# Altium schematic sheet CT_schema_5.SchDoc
size 454 x 430 mm
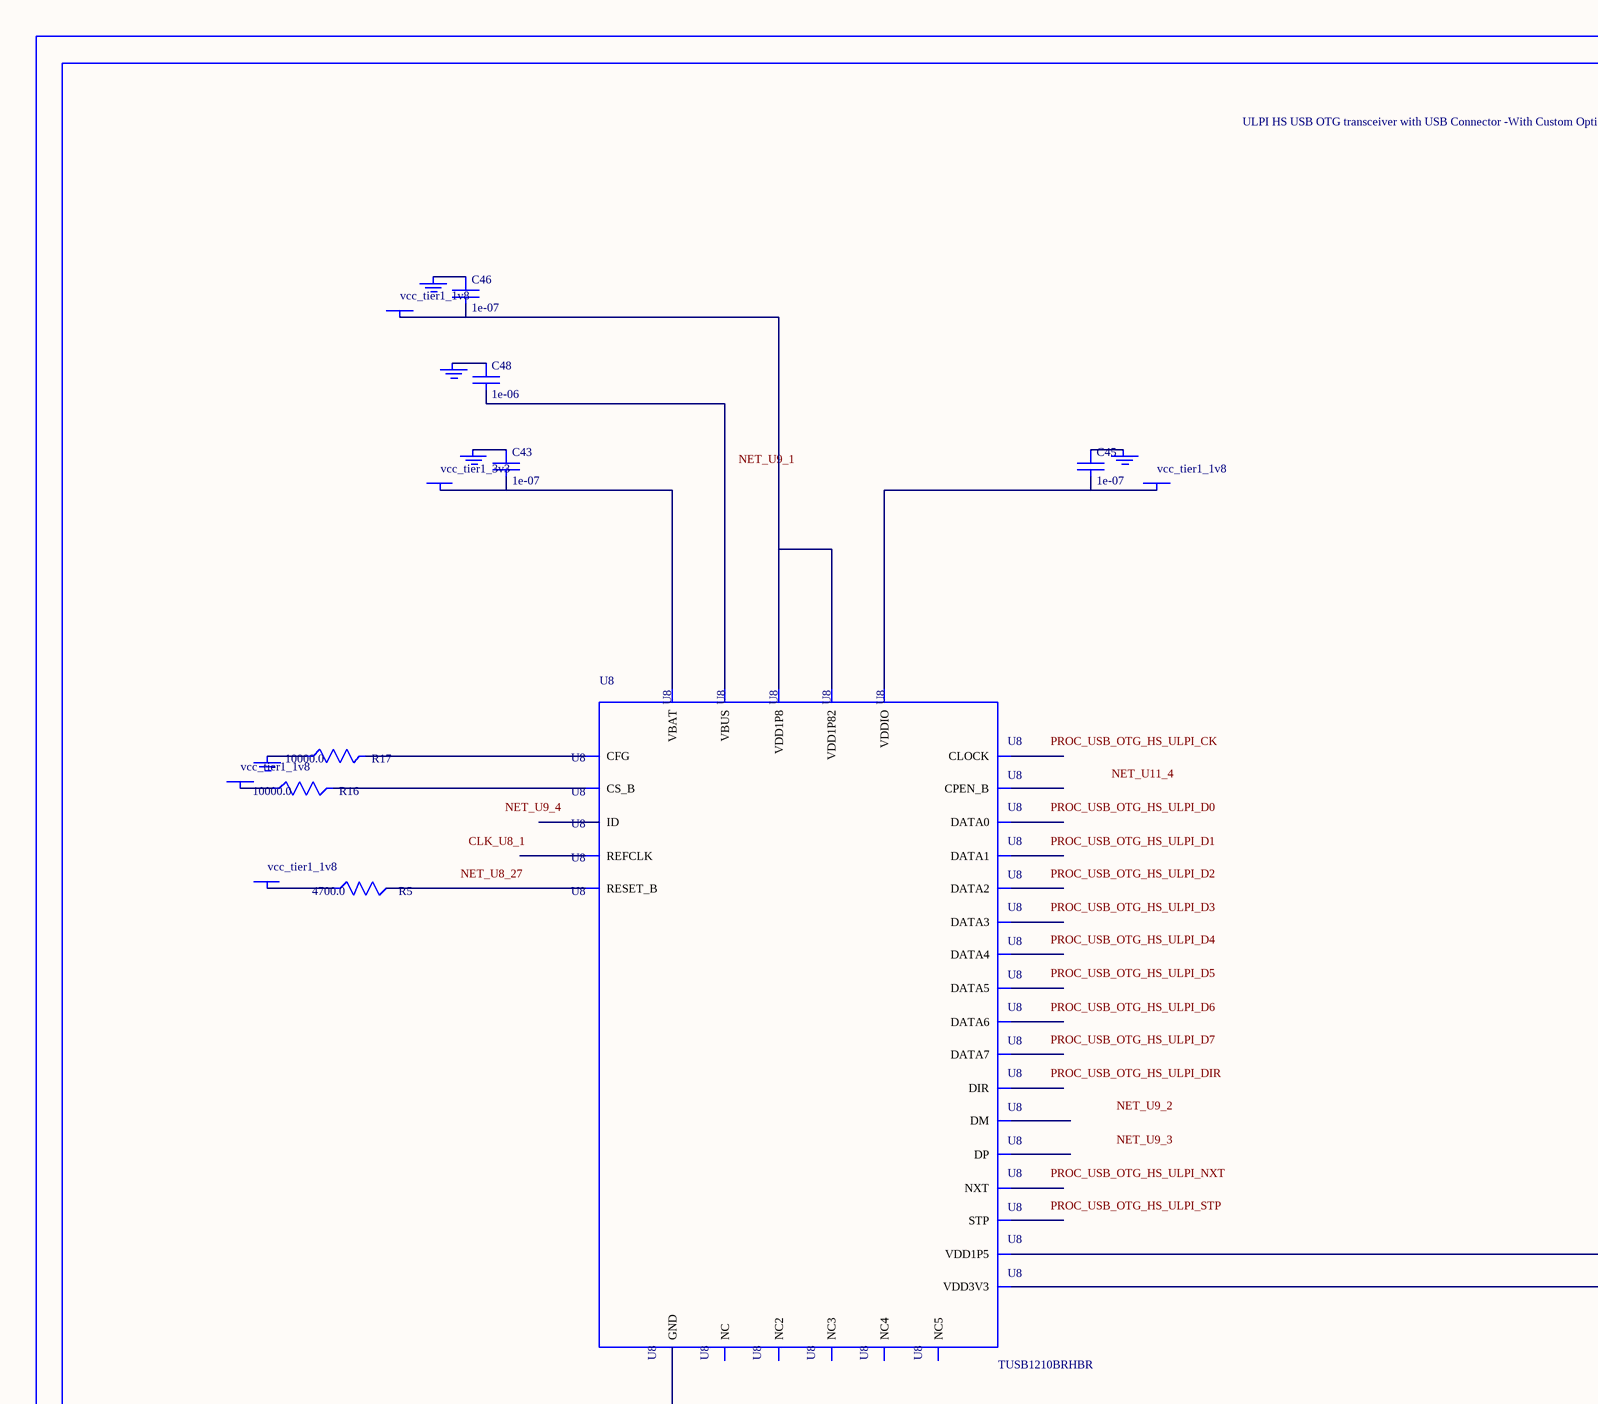
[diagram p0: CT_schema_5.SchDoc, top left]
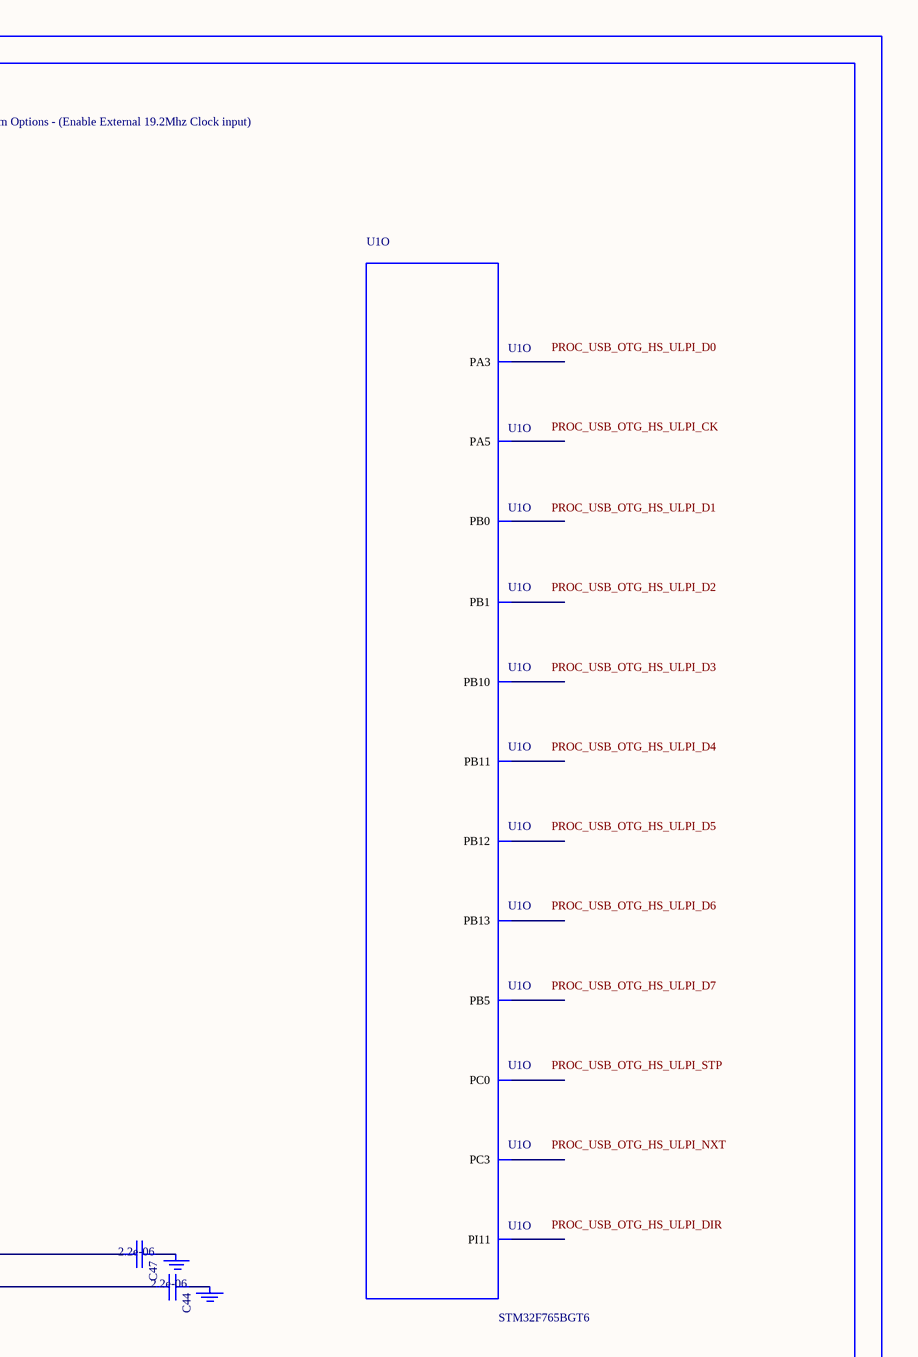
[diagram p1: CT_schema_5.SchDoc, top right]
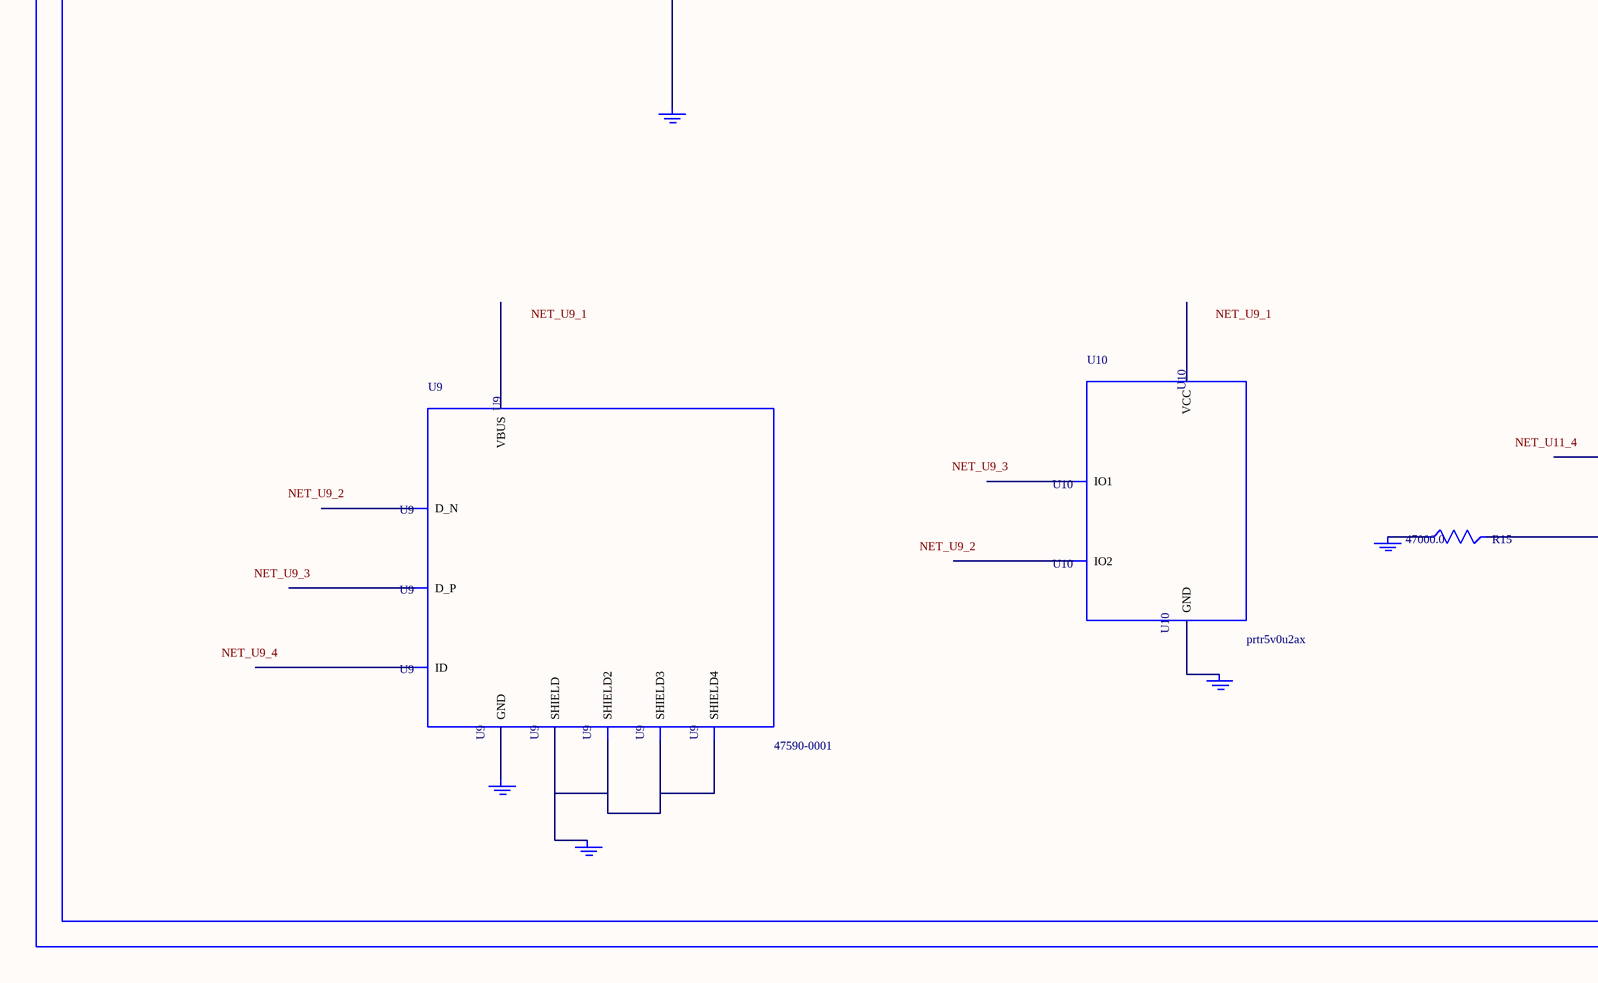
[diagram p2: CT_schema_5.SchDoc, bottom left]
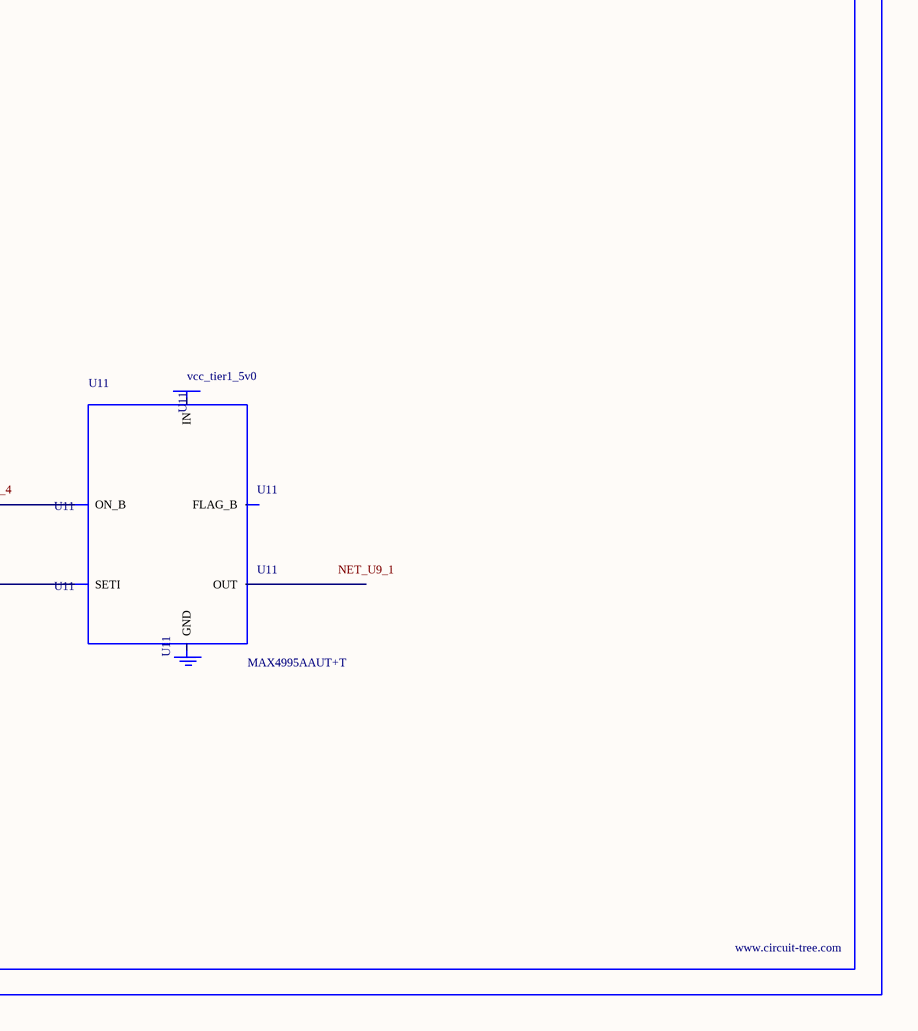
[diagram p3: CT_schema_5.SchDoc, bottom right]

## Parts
BORDER4  (no value)
C43  1e-07  [C0402]
C44  2.2e-06  [C0603]
C45  1e-07  [C0402]
C46  1e-07  [C0402]
C47  2.2e-06  [C0603]
C48  1e-06  [C0603]
GND_INSTANCE_4_0  (no value)
GND_INSTANCE_4_1  (no value)
GND_INSTANCE_4_2  (no value)
GND_INSTANCE_4_3  (no value)
GND_INSTANCE_4_4  (no value)
GND_INSTANCE_4_5  (no value)
GND_INSTANCE_4_6  (no value)
GND_INSTANCE_4_7  (no value)
GND_INSTANCE_4_8  (no value)
GND_INSTANCE_4_9  (no value)
GND_INSTANCE_4_10  (no value)
GND_INSTANCE_4_11  (no value)
GND_INSTANCE_4_12  (no value)
POWER_INSTANCE_4_0  vcc_tier1_1v8
POWER_INSTANCE_4_1  vcc_tier1_3v3
POWER_INSTANCE_4_2  vcc_tier1_1v8
POWER_INSTANCE_4_3  vcc_tier1_1v8
POWER_INSTANCE_4_4  vcc_tier1_1v8
POWER_INSTANCE_4_5  vcc_tier1_5v0
R5  4700.0  [R0603]
R15  47000.0  [R0603]
R16  10000.0  [R0603]
R17  10000.0  [R0603]
U1  STM32F765BGT6  [LQFP208]  (part O of 16)
U8  TUSB1210BRHBR  [RHB32_3P45X3P45]
U9  47590-0001  [MICRO_USB_AB]
U10  prtr5v0u2ax  [SOT143B]
U11  MAX4995AAUT+T  [SOT-23-6]

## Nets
NetC43_1: C43.1 GND_INSTANCE_4_3.0(GND)
NetC43_2: C43.2 POWER_INSTANCE_4_1.0(PWR) U8.21(VBAT)
NetC44_1: C44.1 GND_INSTANCE_4_2.0(GND)
NetC44_2: C44.2 U8.20(VDD3V3)
NetC45_1: C45.1 GND_INSTANCE_4_6.0(GND)
NetC45_2: C45.2 POWER_INSTANCE_4_3.0(PWR) U8.32(VDDIO)
NetC46_1: C46.1 GND_INSTANCE_4_5.0(GND)
NetC46_2: C46.2 POWER_INSTANCE_4_2.0(PWR) U8.28(VDD1P8) U8.30(VDD1P82)
NetC47_1: C47.1 GND_INSTANCE_4_0.0(GND)
NetC47_2: C47.2 U8.12(VDD1P5)
NetC48_1: C48.1 GND_INSTANCE_4_4.0(GND)
NetC48_2: C48.2 U8.22(VBUS)
NetGND_INSTANCE_4_1_0: GND_INSTANCE_4_1.0(GND) R17.1
NetGND_INSTANCE_4_7_0: GND_INSTANCE_4_7.0(GND) U8.33(GND)
NetGND_INSTANCE_4_8_0: GND_INSTANCE_4_8.0(GND) U9.6(SHIELD) U9.7(SHIELD2) U9.8(SHIELD3) U9.9(SHIELD4)
NetGND_INSTANCE_4_9_0: GND_INSTANCE_4_9.0(GND) U9.5(GND)
NetGND_INSTANCE_4_10_0: GND_INSTANCE_4_10.0(GND) U10.1(GND)
NetGND_INSTANCE_4_11_0: GND_INSTANCE_4_11.0(GND) R15.1
NetPOWER_INSTANCE_4_0_0: POWER_INSTANCE_4_0.0(PWR) R16.1
NetPOWER_INSTANCE_4_4_0: POWER_INSTANCE_4_4.0(PWR) R5.1
NetR5_2: R5.2 U8.27(RESET_B)
NetR15_2: R15.2 U11.3(SETI)
NetR16_2: R16.2 U8.11(CS_B)
NetR17_2: R17.2 U8.14(CFG)

Not connected (* = marked no-connect by the designer): GND_INSTANCE_4_12 0(GND); POWER_INSTANCE_4_5 0(PWR); U1 13(PI11) 35(PC0) 38(PC3) 50(PA3) 54(PA5) 61(PB0) 62(PB1) 90(PB10) 91(PB11) 104(PB12) 105(PB13) 194(PB5); U8 1(REFCLK) 2(NXT) 3(DATA0) 4(DATA1) 5(DATA2) 6(DATA3) 7(DATA4) 8(NC) 9(DATA5) 10(DATA6) 13(DATA7) 15(NC2) 16(NC3) 17(CPEN_B) 18(DP) 19(DM) 23(ID) 24(NC4) 25(NC5) 26(CLOCK) 29(STP) 31(DIR); U9 1(VBUS) 2(D_N) 3(D_P) 4(ID); U10 2(IO1) 3(IO2) 4(VCC); U11 1(OUT) 2(GND) 4(ON_B) 5(IN) 6(FLAG_B)

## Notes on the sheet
- Labels drawn without touching a wire or pin: CLK_U8_1, NET_U8_27, NET_U9_1, NET_U9_2, NET_U9_3, NET_U9_4, NET_U11_4, PROC_USB_OTG_HS_ULPI_CK, PROC_USB_OTG_HS_ULPI_D0, PROC_USB_OTG_HS_ULPI_D1, PROC_USB_OTG_HS_ULPI_D2, PROC_USB_OTG_HS_ULPI_D3, PROC_USB_OTG_HS_ULPI_D4, PROC_USB_OTG_HS_ULPI_D5, PROC_USB_OTG_HS_ULPI_D6, PROC_USB_OTG_HS_ULPI_D7, PROC_USB_OTG_HS_ULPI_DIR, PROC_USB_OTG_HS_ULPI_NXT, PROC_USB_OTG_HS_ULPI_STP

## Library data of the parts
BORDER4 = BORDER_PAGE4
C43 C45 C46 = C0402C104K3RACTU
C44 C47 = C0603C225K8RACTU
C48 = C0603C105K3RACTU
GND_INSTANCE_4_0-GND_INSTANCE_4_12 = GND
POWER_INSTANCE_4_0-POWER_INSTANCE_4_5 = PWR
R5 = RC0603JR-074K7L
R15 = RC0603JR-0747KL
R16 R17 = RC0603JR-0710KL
